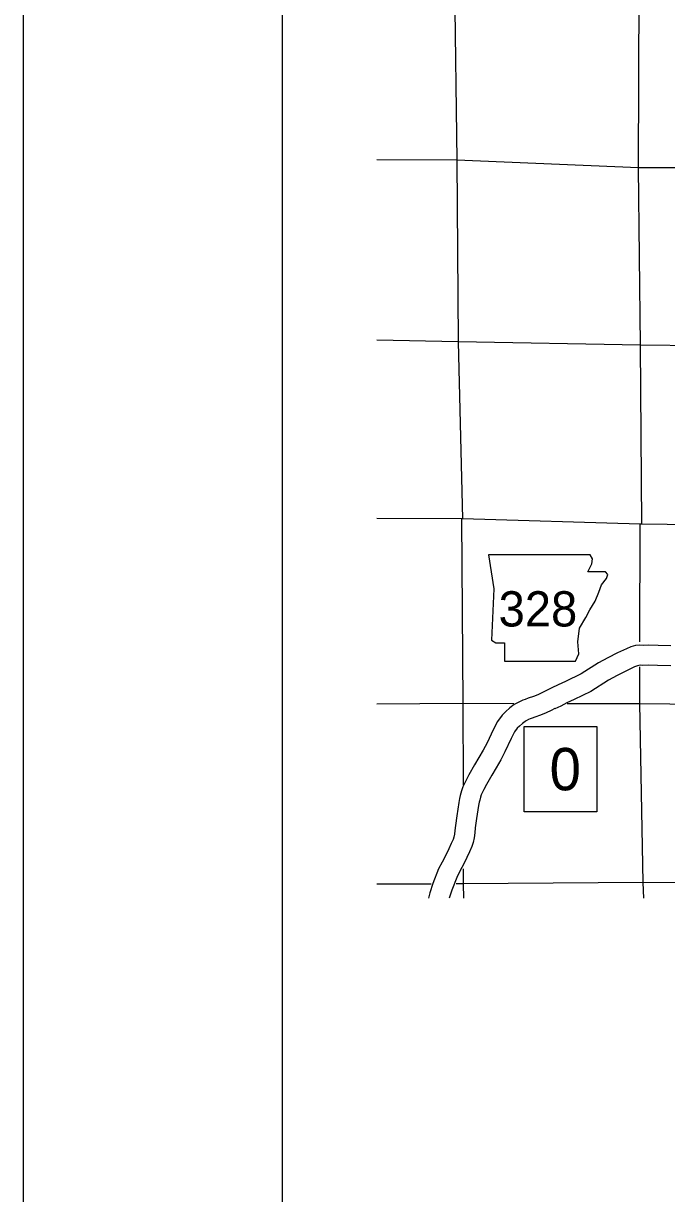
# Model space of a CAD drawing. Extents: x 1369885 to 1370219, y 379980 to 380218.
# Drawn here: x 1369885.4 to 1369916.2, y 380123.6 to 380179.6 of the extents above; entities that cross this region are included whole.
import ezdxf

# ---------------------------------------------------------------- set-up
doc = ezdxf.new("R2010")
doc.units = 0
for name, color, linetype in [('Level 10', 7, 'Continuous'), ('Level 21', 7, 'Continuous'), ('Level 27', 7, 'Continuous'), ('Level 4', 7, 'Continuous'), ('Level 5', 7, 'Continuous'), ('R_No Plot', 7, 'Continuous'), ('STAMP_PE_FOSTER-SIGNATURE', 7, 'Continuous')]:
    doc.layers.add(name, color=color, linetype=linetype)

msp = doc.modelspace()

# ---------------------------------------------------------------- linework, layer by layer
at = {"layer": 'Level 10'}
for points in [[(1369916.389, 380149.781), (1369915.778, 380149.797), (1369915.332, 380149.801), (1369915.064, 380149.796), (1369914.912, 380149.801), (1369914.699, 380149.784), (1369914.484, 380149.728), (1369914.264, 380149.636), (1369913.847, 380149.436), (1369913.378, 380149.2), (1369912.925, 380148.958), (1369912.099, 380148.429), (1369911.358, 380148.074), (1369911, 380147.905), (1369910.703, 380147.757), (1369910.442, 380147.636)], [(1369916.385, 380148.823), (1369915.761, 380148.839), (1369915.338, 380148.843), (1369915.057, 380148.837), (1369914.933, 380148.841), (1369914.859, 380148.836), (1369914.791, 380148.818), (1369914.656, 380148.761), (1369914.27, 380148.576), (1369913.819, 380148.349), (1369913.41, 380148.131), (1369912.566, 380147.59), (1369911.77, 380147.209), (1369911.419, 380147.043), (1369911.119, 380146.894), (1369910.845, 380146.766)], [(1369910.44, 380147.635), (1369910.252, 380147.547), (1369910.02, 380147.436), (1369909.817, 380147.346), (1369909.569, 380147.267), (1369909.415, 380147.207), (1369909.302, 380147.166), (1369909.179, 380147.111), (1369909.017, 380147.031), (1369908.899, 380146.963), (1369908.682, 380146.802), (1369908.48, 380146.622), (1369908.312, 380146.45), (1369908.097, 380146.157), (1369907.895, 380145.759), (1369907.597, 380145.13), (1369907.416, 380144.788), (1369907.204, 380144.423), (1369906.996, 380144.072), (1369906.724, 380143.595), (1369906.583, 380143.32), (1369906.443, 380143.022), (1369906.365, 380142.829), (1369906.31, 380142.617), (1369906.278, 380142.473), (1369906.244, 380142.283), (1369906.144, 380141.643), (1369906.078, 380141.179), (1369906.057, 380140.94), (1369906.031, 380140.758), (1369906, 380140.613), (1369905.965, 380140.508), (1369905.884, 380140.317), (1369905.759, 380140.06), (1369905.616, 380139.752), (1369905.45, 380139.427), (1369905.27, 380139.094), (1369905, 380138.395), (1369904.862, 380137.948), (1369904.787, 380137.69)], [(1369910.847, 380146.767), (1369910.662, 380146.68), (1369910.42, 380146.565), (1369910.156, 380146.449), (1369909.89, 380146.364), (1369909.755, 380146.311), (1369909.662, 380146.277), (1369909.585, 380146.243), (1369909.468, 380146.185), (1369909.425, 380146.16), (1369909.287, 380146.058), (1369909.142, 380145.929), (1369909.044, 380145.829), (1369908.916, 380145.653), (1369908.755, 380145.338), (1369908.454, 380144.701), (1369908.254, 380144.322), (1369908.03, 380143.937), (1369907.824, 380143.591), (1369907.567, 380143.139), (1369907.444, 380142.898), (1369907.321, 380142.637), (1369907.276, 380142.527), (1369907.242, 380142.394), (1369907.218, 380142.285), (1369907.189, 380142.125), (1369907.092, 380141.502), (1369907.03, 380141.068), (1369907.009, 380140.83), (1369906.975, 380140.591), (1369906.926, 380140.359), (1369906.862, 380140.17), (1369906.757, 380139.92), (1369906.625, 380139.649), (1369906.478, 380139.332), (1369906.298, 380138.982), (1369906.143, 380138.693), (1369905.906, 380138.08), (1369905.785, 380137.69)]]:
    msp.add_lwpolyline(points, dxfattribs=at)
at = {"layer": 'Level 21'}
msp.add_lwpolyline([(1369907.67, 380154.126), (1369907.913, 380152.505), (1369907.805, 380150.046), (1369908.021, 380149.911), (1369908.426, 380149.911), (1369908.426, 380149.046), (1369911.831, 380149.046), (1369911.993, 380149.397), (1369911.939, 380149.965), (1369912.02, 380150.613), (1369912.318, 380151.127), (1369912.507, 380151.505), (1369912.777, 380151.911), (1369912.939, 380152.343), (1369913.074, 380152.694), (1369913.317, 380152.991), (1369913.371, 380153.181), (1369913.263, 380153.316), (1369912.426, 380153.316), (1369912.615, 380153.694), (1369912.642, 380153.937), (1369912.53, 380154.124)], close=True, dxfattribs=at)
at = {"layer": 'Level 27'}
msp.add_lwpolyline([(1369909.364, 380145.917), (1369912.853, 380145.917), (1369912.853, 380141.829), (1369909.364, 380141.829)], close=True, dxfattribs=at)
at = {"layer": 'Level 4'}
msp.add_lwpolyline([(1369926.278, 380155.441), (1369923.502, 380155.488), (1369923.441, 380155.484), (1369914.997, 380155.591), (1369914.93, 380155.597), (1369906.42, 380155.85), (1369906.378, 380155.851), (1369902.311, 380155.872)], dxfattribs=at)
at = {"layer": 'Level 5'}
for points in [[(1369905.738, 380203.537), (1369905.818, 380198.693), (1369905.933, 380190.092), (1369906.032, 380181.452), (1369906.147, 380173.018), (1369906.209, 380164.33), (1369906.42, 380155.85)], [(1369914.997, 380155.591), (1369914.944, 380164.166), (1369914.846, 380172.646), (1369914.877, 380181.207), (1369914.855, 380182.213)], [(1369924.364, 380172.638), (1369923.318, 380172.66), (1369914.846, 380172.646), (1369906.147, 380173.018), (1369902.311, 380173.036)], [(1369929.799, 380163.946), (1369923.407, 380164.071), (1369914.944, 380164.166), (1369906.209, 380164.33), (1369902.311, 380164.411)], [(1369906.378, 380155.851), (1369906.439, 380147.023), (1369906.448, 380143.107)], [(1369914.913, 380149.973), (1369914.93, 380155.597)], [(1369915.071, 380138.448), (1369914.904, 380147.01), (1369914.909, 380148.763)], [(1369902.311, 380146.997), (1369906.439, 380147.023), (1369908.875, 380147.019)], [(1369911.437, 380147.015), (1369914.904, 380147.01), (1369923.487, 380146.925), (1369932.115, 380146.851)], [(1369906.456, 380139.105), (1369906.458, 380138.378)], [(1369931.463, 380138.317), (1369923.615, 380138.382), (1369915.071, 380138.448), (1369906.458, 380138.378), (1369906.118, 380138.377)], [(1369915.095, 380137.69), (1369915.071, 380138.448)], [(1369904.926, 380138.372), (1369902.311, 380138.361)], [(1369906.458, 380138.378), (1369906.462, 380137.69)]]:
    msp.add_lwpolyline(points, dxfattribs=at)
at = {"layer": 'R_No Plot'}
msp.add_lwpolyline([(1369885.401, 380217.922), (1370218.741, 380217.922), (1370218.741, 380004.585), (1369885.401, 380004.585)], close=True, dxfattribs=at)
at = {"layer": 'STAMP_PE_FOSTER-SIGNATURE'}
msp.add_line((1369897.808, 380008.568), (1369897.808, 380214.028), dxfattribs=at)

# ---------------------------------------------------------------- texts
at = {"layer": 'Level 21'}
msp.add_text('328', height=1.6867, dxfattribs=at).set_placement((1369908.149, 380150.7))
at = {"layer": 'Level 27'}
msp.add_text('0', height=2.024, dxfattribs=at).set_placement((1369910.587, 380142.861))

doc.saveas('drawing.dxf')
